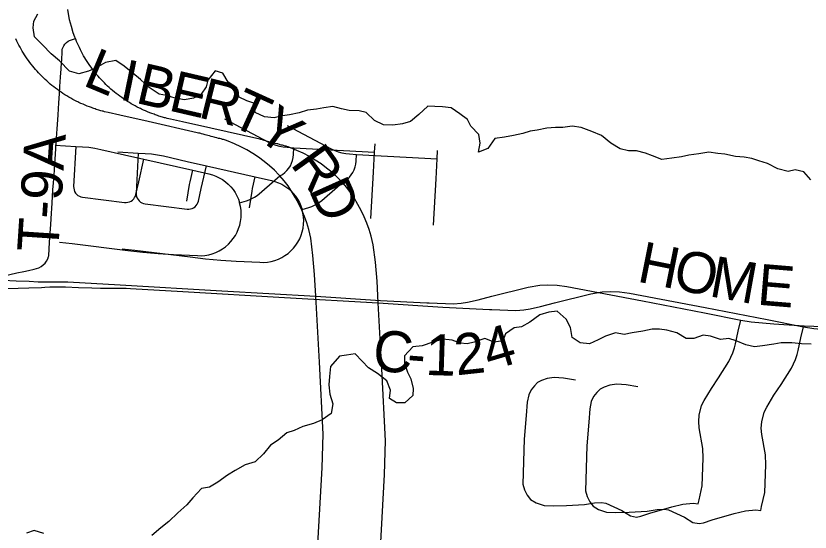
# Model space of a CAD drawing. Extents: x -38.2 to 41.9, y -4 to 24.9.
# Drawn here: x 6.659 to 7.758, y 19.886 to 20.6 of the extents above; entities that cross this region are included whole.
import ezdxf

# ---------------------------------------------------------------- set-up
doc = ezdxf.new("R2010")
doc.units = 0
for name, color, linetype in [('GM_X_County_Road', 7, 'Continuous'), ('GM_X_County_Road_Text', 7, 'Continuous'), ('GM_X_Minor_River', 7, 'Continuous'), ('GM_X_State_Location', 7, 'Continuous'), ('GM_X_Township_Road', 7, 'Continuous'), ('GM_X_Township_Road_Text', 7, 'Continuous')]:
    doc.layers.add(name, color=color, linetype=linetype)

msp = doc.modelspace()

# ---------------------------------------------------------------- linework, layer by layer
at = {"layer": 'GM_X_County_Road'}
for points in [[(7.0231, 20.3802), (7.0169, 20.3867), (7.0099, 20.393), (7.0025, 20.3988), (6.9948, 20.4046), (6.9869, 20.4099), (6.9787, 20.4148), (6.9703, 20.4193), (6.9617, 20.4233), (6.9528, 20.4269), (6.9493, 20.4281), (6.9478, 20.4287), (6.9465, 20.4291), (6.9453, 20.4293), (6.9431, 20.43), (6.9415, 20.4304), (6.9397, 20.4307), (6.9373, 20.4315), (6.935, 20.4322), (6.9335, 20.4326), (6.9316, 20.4331), (6.9294, 20.4336), (6.9271, 20.4342), (6.925, 20.4347), (6.9228, 20.4353), (6.921, 20.4357), (6.9185, 20.4364), (6.9162, 20.437), (6.915, 20.4375), (6.9137, 20.4378), (6.9119, 20.4382), (6.91, 20.4386), (6.8423, 20.454), (6.8033, 20.4629), (6.787, 20.4665), (6.782, 20.4676), (6.7799, 20.4682), (6.7785, 20.4685), (6.7769, 20.4689), (6.7755, 20.4692), (6.774, 20.4697), (6.7724, 20.4701), (6.7706, 20.4709), (6.7689, 20.4715), (6.7672, 20.4722), (6.7657, 20.4727), (6.764, 20.4733), (6.761, 20.4744), (6.7581, 20.4755), (6.7551, 20.4767), (6.7522, 20.4779), (6.7493, 20.4792), (6.7465, 20.4805), (6.7451, 20.4812), (6.7436, 20.4819), (6.7408, 20.4833), (6.738, 20.4848), (6.7353, 20.4863), (6.7325, 20.4879), (6.7298, 20.4895), (6.7271, 20.4911), (6.7245, 20.4928), (6.7218, 20.4946), (6.7192, 20.4964), (6.7167, 20.4982), (6.7142, 20.5001), (6.7117, 20.5021), (6.7092, 20.504), (6.7068, 20.506), (6.7044, 20.5081), (6.702, 20.5102), (6.6997, 20.5124), (6.6974, 20.5145), (6.6952, 20.5168), (6.693, 20.519), (6.6908, 20.5213), (6.6887, 20.5237), (6.6866, 20.526), (6.6846, 20.5284), (6.6826, 20.5309), (6.6806, 20.5334), (6.6787, 20.5359), (6.6768, 20.5384), (6.675, 20.541), (6.6732, 20.5436), (6.6715, 20.5462), (6.6698, 20.5489), (6.6682, 20.5516), (6.6666, 20.5543), (6.6651, 20.5571), (6.6636, 20.5599), (6.6621, 20.5627), (6.6607, 20.5655), (6.6594, 20.5684)], [(7.074, 20.2124), (7.0723, 20.2426), (7.0701, 20.2689), (7.0672, 20.2925), (7.0643, 20.3046), (7.0616, 20.3138), (7.0584, 20.3228), (7.0547, 20.3316), (7.0505, 20.3402), (7.0459, 20.3485), (7.0407, 20.3576), (7.0358, 20.3651), (7.0303, 20.3721), (7.0245, 20.3788), (7.0231, 20.3802)], [(6.6132, 20.2341), (6.6198, 20.2346), (6.6283, 20.2346), (6.6418, 20.2346), (6.6596, 20.2338), (6.6778, 20.2331), (6.6901, 20.2325), (6.7082, 20.2325), (6.7252, 20.2325), (6.7314, 20.2322), (6.8037, 20.228), (6.9442, 20.2197), (7.074, 20.2124)], [(7.2308, 20.2032), (7.2643, 20.202), (7.2751, 20.2027), (7.2839, 20.2043), (7.2984, 20.2073), (7.3177, 20.2124), (7.3677, 20.2248), (7.3838, 20.2275), (7.3947, 20.2283), (7.4077, 20.2275), (7.4212, 20.2258), (7.526, 20.2061), (7.6117, 20.1892), (7.662, 20.1791), (7.6761, 20.177), (7.7074, 20.1743), (7.7496, 20.1716), (7.817, 20.1689), (8.01, 20.1556), (8.0878, 20.1504), (8.1996, 20.1432), (8.3267, 20.1356), (8.386, 20.1327), (8.3896, 20.1314)], [(7.0643, 19.6195), (7.067, 19.6688), (7.0725, 19.7882), (7.0828, 19.9749), (7.0842, 20.0216), (7.0792, 20.1211), (7.074, 20.2124)], [(7.074, 20.2124), (7.1634, 20.2065), (7.2277, 20.2033), (7.2308, 20.2032)]]:
    msp.add_lwpolyline(points, dxfattribs=at)
at = {"layer": 'GM_X_Minor_River'}
for points in [[(7.2735, 20.4649), (7.2614, 20.4729), (7.2493, 20.4744), (7.2387, 20.4751), (7.2289, 20.4755), (7.2164, 20.4638), (7.205, 20.4543), (7.1941, 20.4509), (7.1808, 20.449), (7.1676, 20.4497), (7.1551, 20.4554), (7.1437, 20.4664), (7.1339, 20.4691), (7.1203, 20.4695), (7.1097, 20.4717), (7.0976, 20.4748), (7.0854, 20.4732), (7.0752, 20.471), (7.0627, 20.4698), (7.051, 20.466), (7.0378, 20.4634), (7.0279, 20.4619), (7.0166, 20.4592), (7.003, 20.4607), (6.9901, 20.4664), (6.9886, 20.4793), (6.9787, 20.4827), (6.9681, 20.488), (6.9647, 20.5005), (6.953, 20.5085), (6.9454, 20.521), (6.9348, 20.5244), (6.9246, 20.5115), (6.9227, 20.5021), (6.9155, 20.4918), (6.9049, 20.4865), (6.8924, 20.4839), (6.8796, 20.4865), (6.8675, 20.4899), (6.8576, 20.4918), (6.8436, 20.5013), (6.8315, 20.5123), (6.8209, 20.521), (6.8092, 20.5305), (6.7978, 20.5385), (6.7831, 20.5358), (6.7702, 20.5282), (6.76, 20.5237), (6.7463, 20.5203), (6.7335, 20.524), (6.7198, 20.5381), (6.7081, 20.5479), (6.6964, 20.5601), (6.685, 20.5714), (6.6835, 20.5836), (6.6843, 20.593), (6.6896, 20.6033)], [(7.7587, 20.3736), (7.7489, 20.3846), (7.7371, 20.3872), (7.7273, 20.385), (7.7129, 20.3887), (7.6989, 20.3959), (7.6868, 20.3997), (7.677, 20.4028), (7.6664, 20.405), (7.6543, 20.4058), (7.6399, 20.4088), (7.63, 20.41), (7.6176, 20.4115), (7.6036, 20.4096), (7.5899, 20.4077), (7.5797, 20.4054), (7.5665, 20.4035), (7.5528, 20.4016), (7.5396, 20.4065), (7.5298, 20.4103), (7.5176, 20.4137), (7.5067, 20.4134), (7.4949, 20.4164), (7.4821, 20.424), (7.4692, 20.4346), (7.456, 20.4403), (7.4412, 20.4456), (7.4287, 20.4479), (7.4155, 20.446), (7.4056, 20.4456), (7.3935, 20.4448), (7.3803, 20.4422), (7.3704, 20.4406), (7.3602, 20.4376), (7.3473, 20.4346), (7.3349, 20.4323), (7.3216, 20.4304), (7.3118, 20.4168), (7.2993, 20.4118), (7.3012, 20.424), (7.2997, 20.4361), (7.2887, 20.4475), (7.2841, 20.4569), (7.2735, 20.4649)], [(7.7592, 20.1461), (7.7455, 20.1465), (7.7323, 20.148), (7.7175, 20.1477), (7.7073, 20.1461), (7.6918, 20.1439), (7.6808, 20.1424), (7.6687, 20.145), (7.6555, 20.1507), (7.6453, 20.1537), (7.6335, 20.1526), (7.6199, 20.1571), (7.6097, 20.1583), (7.5968, 20.1541), (7.5862, 20.1537), (7.5734, 20.1617), (7.5594, 20.1655), (7.5495, 20.167), (7.5393, 20.1666), (7.5264, 20.164), (7.5117, 20.1617), (7.5003, 20.1594), (7.4886, 20.1617), (7.4746, 20.1571), (7.4647, 20.1522), (7.4526, 20.1465), (7.4398, 20.1477), (7.4284, 20.1552), (7.4261, 20.1693), (7.4201, 20.1806), (7.408, 20.1916), (7.3962, 20.1905), (7.3841, 20.1867), (7.3701, 20.1765), (7.3584, 20.17), (7.3482, 20.1685), (7.3365, 20.1605), (7.3327, 20.1507), (7.3206, 20.1488), (7.3077, 20.1537), (7.2933, 20.1488), (7.2835, 20.1465), (7.2736, 20.1473), (7.2627, 20.1514), (7.2498, 20.153), (7.2358, 20.1488), (7.221, 20.1439), (7.2085, 20.1423), (7.1968, 20.1298), (7.1968, 20.1204), (7.201, 20.1075), (7.2055, 20.098), (7.2086, 20.0847), (7.2082, 20.0749), (7.1972, 20.065), (7.1859, 20.0647), (7.176, 20.0711), (7.1772, 20.0825), (7.1722, 20.0954), (7.1594, 20.1056), (7.1469, 20.1132), (7.1382, 20.1226), (7.1287, 20.1329), (7.1166, 20.131), (7.1067, 20.1295), (7.0946, 20.1151), (7.0931, 20.1014), (7.092, 20.09)], [(7.092, 20.09), (7.0935, 20.0768), (7.0977, 20.0635), (7.0954, 20.0503), (7.0829, 20.0412), (7.0708, 20.0362), (7.0564, 20.0321), (7.044, 20.0264), (7.0341, 20.0234), (7.022, 20.0131), (7.0114, 20.0063), (7.0016, 19.9942), (6.9902, 19.9832), (6.9766, 19.979), (6.9626, 19.9711), (6.952, 19.9646), (6.9388, 19.9551), (6.927, 19.9483), (6.9161, 19.9464), (6.904, 19.9335), (6.8956, 19.9237), (6.8832, 19.9127), (6.8707, 19.9006), (6.8597, 19.8919), (6.8472, 19.8813)], [(6.6981, 19.8843), (6.6845, 19.8881), (6.6739, 19.8847)]]:
    msp.add_lwpolyline(points, dxfattribs=at)
at = {"layer": 'GM_X_State_Location'}
msp.add_line((7.2419, 20.4027), (7.2425, 20.414), dxfattribs=at)
for points in [[(6.6413, 20.24), (6.6606, 20.2449), (6.6703, 20.2468), (6.6766, 20.248), (6.6845, 20.2498), (6.688, 20.2506), (6.6913, 20.2518), (6.6944, 20.2535), (6.6972, 20.2556), (6.6997, 20.2581), (6.7018, 20.2609), (6.7034, 20.2639), (6.7047, 20.2672), (6.7049, 20.2681), (6.7059, 20.2874), (6.7075, 20.3116), (6.7088, 20.3272), (6.7091, 20.3339), (6.7101, 20.3498), (6.7107, 20.3598), (6.7121, 20.3788), (6.7127, 20.3882), (6.7137, 20.4019), (6.7155, 20.4311), (6.7166, 20.4442), (6.7177, 20.4627), (6.7183, 20.4719), (6.7189, 20.4796), (6.7197, 20.4929), (6.7203, 20.5027), (6.7211, 20.5156), (6.7218, 20.5269), (6.7219, 20.5283), (6.7227, 20.5405), (6.7232, 20.5497), (6.7234, 20.5525), (6.7236, 20.5541), (6.7239, 20.5551), (6.7242, 20.5562), (6.7255, 20.5589), (6.7272, 20.5613), (6.7293, 20.5635), (6.7318, 20.5652), (6.7336, 20.5661), (6.7416, 20.5691)], [(7.0345, 20.4487), (7.0953, 20.4164), (7.1002, 20.4141), (7.1052, 20.4122), (7.1103, 20.4108), (7.1156, 20.4098), (7.1209, 20.4093), (7.1303, 20.4087), (7.2419, 20.4027)], [(6.8004, 20.412), (6.8287, 20.4105), (6.8382, 20.41), (6.8467, 20.4092), (6.8551, 20.4081), (6.8635, 20.4064), (6.8962, 20.399), (6.923, 20.3929), (6.9904, 20.3776), (7.0127, 20.3725), (7.0176, 20.3712), (7.0224, 20.3694), (7.027, 20.3672), (7.0314, 20.3646), (7.0355, 20.3617), (7.0394, 20.3583), (7.043, 20.3547), (7.0462, 20.3507), (7.049, 20.3465), (7.0515, 20.342), (7.0535, 20.3374), (7.0552, 20.3325)], [(6.8287, 20.4105), (6.8257, 20.3549), (6.8258, 20.3526), (6.8262, 20.3503), (6.8271, 20.348), (6.8283, 20.346), (6.8298, 20.3442), (6.8316, 20.3426), (6.8336, 20.3414), (6.8359, 20.3406), (6.8382, 20.3401), (6.8963, 20.333), (6.8986, 20.3329), (6.9009, 20.3332), (6.9031, 20.3338), (6.9052, 20.3348), (6.9071, 20.3362), (6.9088, 20.3378), (6.9101, 20.3397), (6.9112, 20.3417), (6.9119, 20.3439), (6.9158, 20.3615), (6.923, 20.3929)], [(7.0552, 20.3325), (7.0647, 20.3353), (7.0686, 20.3366), (7.0723, 20.3382), (7.0759, 20.3402), (7.0793, 20.3424), (7.0825, 20.345), (7.104, 20.3636), (7.1041, 20.3636), (7.111, 20.3696), (7.1145, 20.3717), (7.1177, 20.3743), (7.1198, 20.3763), (7.1206, 20.3771), (7.1232, 20.3803), (7.1253, 20.3837), (7.1271, 20.3874), (7.1285, 20.3913), (7.1294, 20.3952), (7.1298, 20.3993), (7.1303, 20.4087)], [(7.2369, 20.3106), (7.2404, 20.3749), (7.2419, 20.4027)], [(6.9824, 20.3346), (6.986, 20.3578), (6.9867, 20.3615), (6.9904, 20.3776)], [(6.8064, 20.2781), (6.8238, 20.276), (6.9005, 20.2667), (6.9216, 20.2643), (6.9427, 20.2625), (6.9639, 20.2611), (6.9969, 20.2593), (7.0021, 20.2592), (7.0073, 20.2597), (7.0125, 20.2606), (7.0175, 20.2619), (7.0224, 20.2637), (7.0271, 20.266), (7.0315, 20.2686), (7.0358, 20.2717), (7.0397, 20.2751), (7.0433, 20.2789), (7.0465, 20.2829), (7.0494, 20.2873), (7.0518, 20.2919), (7.0539, 20.2967), (7.0554, 20.3017), (7.0566, 20.3067), (7.0572, 20.3119), (7.0574, 20.3171), (7.0571, 20.3223), (7.0564, 20.3275), (7.0552, 20.3325)], [(7.5196, 20.0869), (7.5032, 20.0896), (7.4903, 20.0905), (7.4805, 20.0893), (7.4727, 20.0866), (7.4673, 20.0836), (7.4628, 20.0791), (7.4583, 20.0737), (7.455, 20.0666), (7.453, 20.0565), (7.4515, 20.038), (7.4488, 20.0056), (7.447, 19.9432), (7.4494, 19.9355), (7.453, 19.9281), (7.4577, 19.9218), (7.4651, 19.9171), (7.4761, 19.9138), (7.4892, 19.9132), (7.5073, 19.9135), (7.5323, 19.915), (7.5461, 19.9174), (7.5558, 19.9179), (7.5616, 19.9168), (7.584, 19.9065), (7.5956, 19.8995), (7.6041, 19.8977), (7.61, 19.8988), (7.6224, 19.9029), (7.6527, 19.9116), (7.6682, 19.9155), (7.6826, 19.917), (7.6895, 19.916), (7.6905, 19.9214), (7.6948, 19.941), (7.6963, 19.9792), (7.696, 19.9927), (7.6907, 20.0211), (7.69, 20.03), (7.6907, 20.0388), (7.6941, 20.0518), (7.6977, 20.0591), (7.7077, 20.0753), (7.7175, 20.0901), (7.7317, 20.113), (7.7374, 20.1249), (7.7397, 20.1317), (7.7411, 20.1371), (7.7447, 20.155), (7.7484, 20.1699)]]:
    msp.add_lwpolyline(points, dxfattribs=at)
at = {"layer": 'GM_X_Township_Road'}
msp.add_line((7.1554, 20.4119), (7.156, 20.4232), dxfattribs=at)
for points in [[(6.948, 20.4579), (7.0089, 20.4256), (7.0137, 20.4233), (7.0187, 20.4214), (7.0238, 20.4199), (7.0291, 20.419), (7.0344, 20.4184), (7.0439, 20.4179), (7.1554, 20.4119)], [(6.7139, 20.4212), (6.7423, 20.4197), (6.7517, 20.4191), (6.7602, 20.4184), (6.7687, 20.4173), (6.777, 20.4156), (6.8097, 20.4082), (6.8365, 20.4021), (6.9039, 20.3868), (6.9263, 20.3817), (6.9312, 20.3804), (6.9359, 20.3786), (6.9405, 20.3764), (6.9449, 20.3738), (6.9491, 20.3708), (6.9529, 20.3675), (6.9565, 20.3639), (6.9597, 20.3599), (6.9625, 20.3557), (6.965, 20.3512), (6.967, 20.3465), (6.9687, 20.3417)], [(6.7423, 20.4197), (6.7392, 20.3641), (6.7393, 20.3618), (6.7398, 20.3594), (6.7406, 20.3572), (6.7418, 20.3552), (6.7433, 20.3534), (6.7451, 20.3518), (6.7472, 20.3506), (6.7494, 20.3498), (6.7517, 20.3493), (6.8098, 20.3422), (6.8121, 20.3421), (6.8144, 20.3424), (6.8166, 20.343), (6.8187, 20.344), (6.8206, 20.3454), (6.8223, 20.347), (6.8236, 20.3489), (6.8247, 20.3509), (6.8254, 20.3531), (6.8294, 20.3707), (6.8365, 20.4021)], [(6.9687, 20.3417), (6.9782, 20.3445), (6.9821, 20.3458), (6.9858, 20.3474), (6.9894, 20.3494), (6.9928, 20.3516), (6.996, 20.3541), (7.0176, 20.3728), (7.0176, 20.3728), (7.0245, 20.3788), (7.028, 20.3809), (7.0312, 20.3835), (7.0333, 20.3855), (7.0341, 20.3863), (7.0367, 20.3895), (7.0389, 20.3929), (7.0406, 20.3966), (7.042, 20.4004), (7.0429, 20.4044), (7.0434, 20.4085), (7.0439, 20.4179)], [(7.1504, 20.3198), (7.1539, 20.3841), (7.1554, 20.4119)], [(6.8959, 20.3438), (6.8995, 20.367), (6.9003, 20.3707), (6.9039, 20.3868)], [(6.7199, 20.2873), (6.7373, 20.2852), (6.814, 20.2758), (6.8351, 20.2735), (6.8562, 20.2716), (6.8774, 20.2703), (6.9104, 20.2685), (6.9157, 20.2684), (6.9208, 20.2688), (6.926, 20.2697), (6.931, 20.2711), (6.9359, 20.2729), (6.9406, 20.2752), (6.9451, 20.2778), (6.9493, 20.2809), (6.9532, 20.2843), (6.9568, 20.2881), (6.96, 20.2921), (6.9629, 20.2965), (6.9654, 20.3011), (6.9674, 20.3059), (6.969, 20.3108), (6.9701, 20.3159), (6.9707, 20.3211), (6.9709, 20.3263), (6.9707, 20.3315), (6.9699, 20.3367), (6.9687, 20.3417)], [(7.4331, 20.0961), (7.4167, 20.0988), (7.4038, 20.0997), (7.394, 20.0985), (7.3862, 20.0958), (7.3808, 20.0928), (7.3763, 20.0883), (7.3718, 20.0829), (7.3686, 20.0758), (7.3665, 20.0657), (7.365, 20.0472), (7.3623, 20.0148), (7.3606, 19.9524), (7.3629, 19.9447), (7.3665, 19.9373), (7.3712, 19.931), (7.3787, 19.9263), (7.3897, 19.923), (7.4027, 19.9224), (7.4209, 19.9227), (7.4458, 19.9242), (7.4596, 19.9266), (7.4694, 19.9271), (7.4751, 19.926), (7.4975, 19.9157), (7.5091, 19.9087), (7.5176, 19.9069), (7.5235, 19.9079), (7.5359, 19.9121), (7.5662, 19.9208), (7.5817, 19.9247), (7.5961, 19.9262), (7.603, 19.9252), (7.6041, 19.9306), (7.6083, 19.9502), (7.6099, 19.9884), (7.6095, 20.0019), (7.6042, 20.0303), (7.6036, 20.0391), (7.6043, 20.048), (7.6076, 20.061), (7.6112, 20.0683), (7.6212, 20.0845), (7.631, 20.0993), (7.6452, 20.1222), (7.6509, 20.1341), (7.6532, 20.1409), (7.6546, 20.1463), (7.6582, 20.1642), (7.662, 20.1791)]]:
    msp.add_lwpolyline(points, dxfattribs=at)
at = {"layer": 'GM_X_Township_Road_Text'}
for points in [[(7.1096, 20.371), (7.1034, 20.3775), (7.0963, 20.3838), (7.0889, 20.3896), (7.0813, 20.3954), (7.0734, 20.4007), (7.0652, 20.4056), (7.0568, 20.4101), (7.0481, 20.4141), (7.0393, 20.4177), (7.0358, 20.419), (7.0342, 20.4195), (7.0329, 20.4199), (7.0318, 20.4201), (7.0295, 20.4208), (7.0279, 20.4212), (7.0262, 20.4216), (7.0238, 20.4223), (7.0214, 20.423), (7.02, 20.4234), (7.0181, 20.4239), (7.0158, 20.4244), (7.0136, 20.425), (7.0114, 20.4255), (7.0093, 20.4261), (7.0074, 20.4265), (7.005, 20.4272), (7.0027, 20.4278), (7.0015, 20.4283), (7.0002, 20.4286), (6.9983, 20.429), (6.9965, 20.4295), (6.9288, 20.4448), (6.8898, 20.4537), (6.8734, 20.4573), (6.8685, 20.4584), (6.8664, 20.459), (6.865, 20.4593), (6.8634, 20.4597), (6.862, 20.4601), (6.8605, 20.4605), (6.8589, 20.461), (6.8571, 20.4617), (6.8553, 20.4623), (6.8537, 20.463), (6.8522, 20.4635), (6.8505, 20.4642), (6.8475, 20.4652), (6.8446, 20.4663), (6.8416, 20.4675), (6.8387, 20.4687), (6.8358, 20.47), (6.833, 20.4713), (6.8315, 20.472), (6.8301, 20.4727), (6.8273, 20.4741), (6.8245, 20.4756), (6.8217, 20.4771), (6.819, 20.4787), (6.8163, 20.4803), (6.8136, 20.4819), (6.8109, 20.4836), (6.8083, 20.4854), (6.8057, 20.4872), (6.8032, 20.489), (6.8006, 20.4909), (6.7981, 20.4929), (6.7957, 20.4948), (6.7932, 20.4969), (6.7909, 20.4989), (6.7885, 20.501), (6.7862, 20.5032), (6.7839, 20.5053), (6.7817, 20.5076), (6.7795, 20.5098), (6.7773, 20.5121), (6.7752, 20.5145), (6.7731, 20.5168), (6.771, 20.5192), (6.769, 20.5217), (6.7671, 20.5242), (6.7652, 20.5267), (6.7633, 20.5292), (6.7615, 20.5318), (6.7597, 20.5344), (6.758, 20.537), (6.7563, 20.5397), (6.7547, 20.5424), (6.7531, 20.5451), (6.7515, 20.5479), (6.75, 20.5507), (6.7486, 20.5535), (6.7472, 20.5563), (6.7458, 20.5592), (6.7445, 20.562), (6.7433, 20.5649), (6.7421, 20.5679), (6.7416, 20.5691), (6.741, 20.5708), (6.7388, 20.5767), (6.7361, 20.5854), (6.7337, 20.595), (6.7311, 20.6089)], [(7.1605, 20.2032), (7.1588, 20.2334), (7.1565, 20.2597), (7.1536, 20.2833), (7.1508, 20.2954), (7.1481, 20.3046), (7.1448, 20.3136), (7.1412, 20.3224), (7.137, 20.331), (7.1324, 20.3394), (7.1272, 20.3484), (7.1223, 20.3559), (7.1168, 20.3629), (7.111, 20.3696), (7.1096, 20.371)], [(6.4936, 20.2294), (6.5094, 20.2281), (6.5257, 20.2265), (6.5608, 20.2244), (6.5716, 20.2237), (6.5869, 20.2226), (6.6003, 20.2223), (6.6143, 20.2218), (6.6297, 20.2223), (6.6476, 20.2229), (6.6775, 20.2239), (6.6949, 20.2246), (6.6996, 20.2249)], [(6.6996, 20.2249), (6.7062, 20.2254), (6.7148, 20.2254), (6.7282, 20.2254), (6.746, 20.2246), (6.7643, 20.2239), (6.7766, 20.2233), (6.7946, 20.2233), (6.8117, 20.2233), (6.8178, 20.223), (6.8901, 20.2188), (7.0307, 20.2105), (7.1605, 20.2032)], [(7.3173, 20.194), (7.3507, 20.1928), (7.3616, 20.1935), (7.3704, 20.1951), (7.3849, 20.1981), (7.4042, 20.2032), (7.4542, 20.2157), (7.4703, 20.2183), (7.4812, 20.2191), (7.4942, 20.2183), (7.5077, 20.2166), (7.6125, 20.1969), (7.6982, 20.1801), (7.7484, 20.1699), (7.7626, 20.1678), (7.7939, 20.1651), (7.8361, 20.1624), (7.9035, 20.1597), (8.0965, 20.1465), (8.1743, 20.1412), (8.2861, 20.134), (8.4132, 20.1264), (8.4725, 20.1235), (8.4761, 20.1222)], [(7.1508, 19.6103), (7.1535, 19.6596), (7.159, 19.7791), (7.1692, 19.9657), (7.1706, 20.0124), (7.1656, 20.1119), (7.1605, 20.2032)], [(7.1605, 20.2032), (7.2499, 20.1973), (7.3141, 20.1941), (7.3173, 20.194)]]:
    msp.add_lwpolyline(points, dxfattribs=at)

# ---------------------------------------------------------------- texts
at = {"layer": 'GM_X_County_Road_Text'}
for s, rotation, p in [('L', 337.2738, (6.7503, 20.5048)), ('I', 348.4399, (6.8008, 20.4849)), ('B', 346.945, (6.8233, 20.4803)), ('E', 346.9461, (6.8687, 20.4698)), ('R', 346.1143, (6.9099, 20.4602)), ('T', 335.5571, (6.9526, 20.45)), ('Y', 323.9734, (6.9887, 20.4339)), ('R', 305.7169, (7.0379, 20.3953)), ('D', 294.1631, (7.0637, 20.36)), ('H', 348.7205, (7.5169, 20.2329)), ('O', 348.3073, (7.566, 20.2231)), ('M', 349.7534, (7.6166, 20.2126)), ('E', 355.2552, (7.6833, 20.2008)), ('C', 354.5667, (7.1513, 20.11)), ('4', 16.657, (7.3145, 20.1088)), ('1', 358.2285, (7.225, 20.1035)), ('2', 6.1726, (7.2686, 20.1028)), ('-', 355.6785, (7.199, 20.1054))]:
    msp.add_text(s, height=0.0568, rotation=rotation, dxfattribs=at).set_placement(p)
at = {"layer": 'GM_X_Township_Road_Text'}
msp.add_text('T-9A', height=0.05682, rotation=86.2163, dxfattribs=at).set_placement((6.7177, 20.272))

doc.saveas('drawing.dxf')
